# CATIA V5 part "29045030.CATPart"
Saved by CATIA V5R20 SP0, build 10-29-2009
Part number: 29045030
Definition: NONE
Nomenclature: 29045030
Source: Unknown
Description: 29045030
Bounding box of the stored display mesh (mm): x -15 to 44.548, y -36.5 to 71.048, z -26.5 to 26.5
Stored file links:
  C:\Users\Utente\Desktop\IO LAVORO\3D X SITO CF\X SITO\PLASTICA\RF1\29045030.CATPart
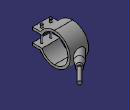
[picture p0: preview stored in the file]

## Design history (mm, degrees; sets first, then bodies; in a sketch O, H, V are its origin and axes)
Body1 "29045030" (main body)
  Solid1: solid without history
